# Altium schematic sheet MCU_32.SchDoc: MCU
size A4; DocumentNumber: MB1180; Revision: C.1; SheetNumber: 2; SheetTotal: 3; Project: NUCLEO32
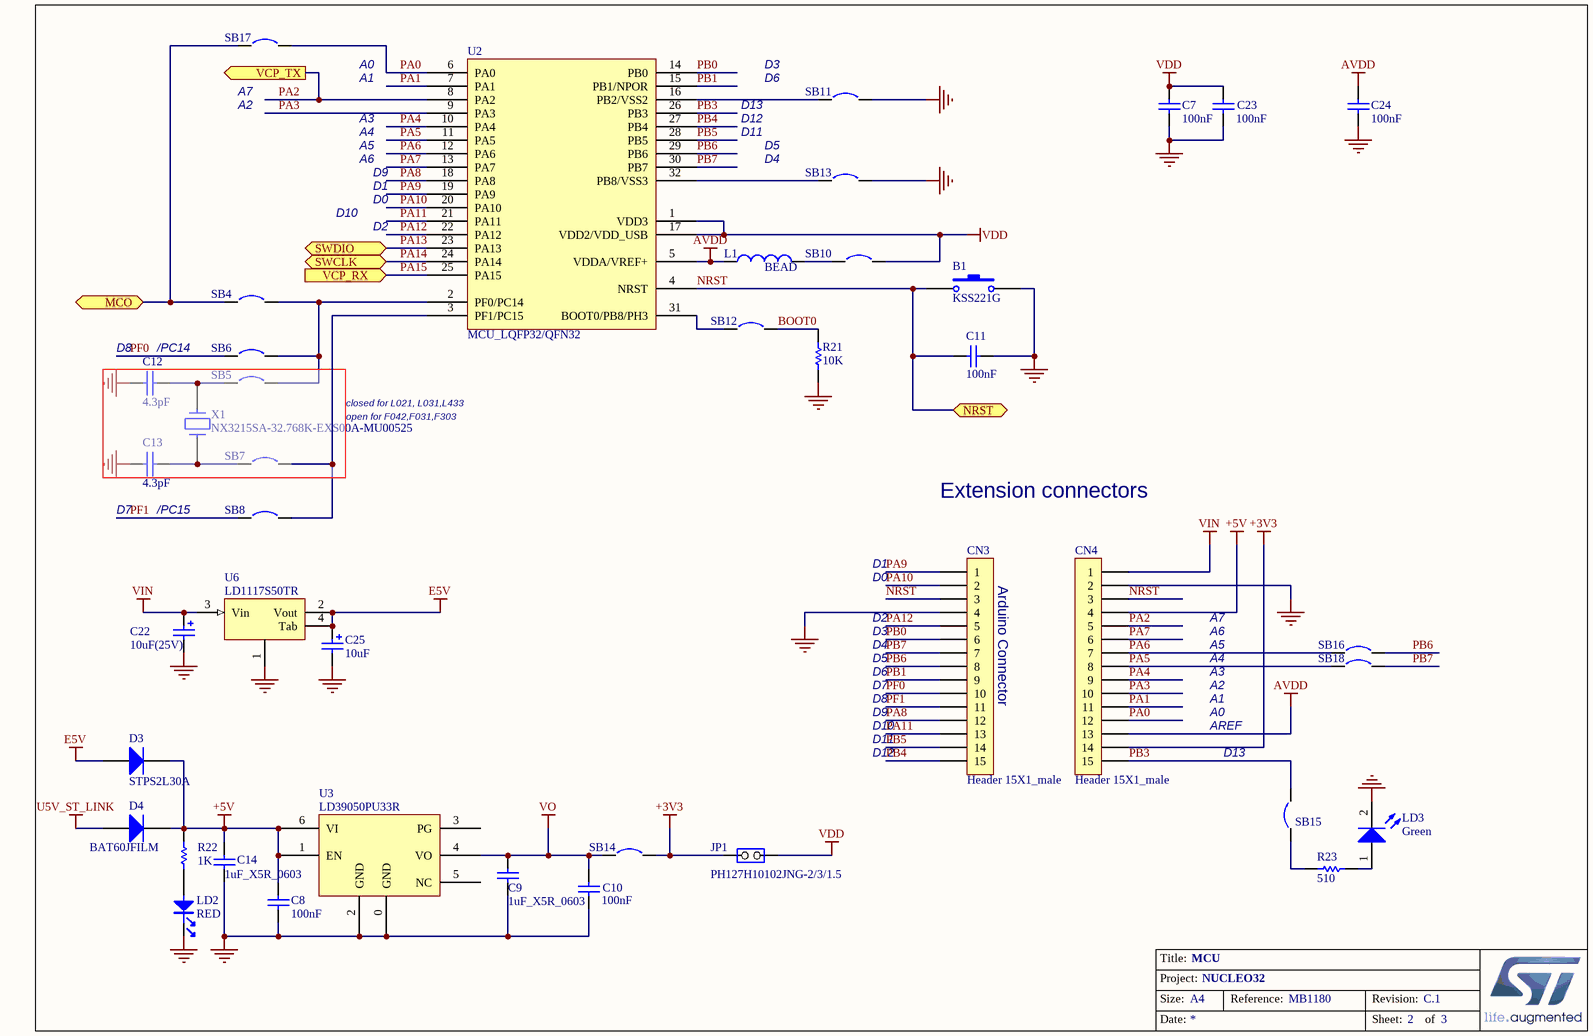
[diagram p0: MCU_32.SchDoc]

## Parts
B1  KSS221G  [SW2_5R6_5R5x3R1]
C7  100nF  [0603C]
C8  100nF  [0603C]
C9  1uF_X5R_0603  [0603C]
C10  100nF  [0603C]
C11  100nF  [0603C]
C12  4.3pF  [0603C]
C13  4.3pF  [0603C]
C14  1uF_X5R_0603  [0603C]
C22  10uF(25V)  [TAN_B]
C23  100nF  [0603C]
C24  100nF  [0603C]
C25  10uF  [TAN_A]
CN3  Header 15X1_male  [HDR_1x15_2R54_V_F]
CN4  Header 15X1_male  [HDR_1x15_2R54_V_F]
D3  STPS2L30A  [SMA]
D4  BAT60JFILM  [SOD-323]
JP1  PH127H10102JNG-2/3/1.5  [HDR_1x2_1R27_R_M]
L1  BEAD  [0603L]
LD2  RED  [0603D_R]
LD3  Green  [0603D_G]
R21  10K  [0603R]
R22  1K  [0603R]
R23  510  [0603R]
SB4  Circuit Breaker (open)  [SB_0603]  (value not drawn)
SB5  Circuit Breaker  [SB_0603]  (value not drawn)
SB6  Circuit Breaker  [SB_0603]  (value not drawn)
SB7  Circuit Breaker  [SB_0603]  (value not drawn)
SB8  Circuit Breaker  [SB_0603]  (value not drawn)
SB10  Circuit Breaker (close)  [SB_0603]  (value not drawn)
SB11  Circuit Breaker (close)  [SB_0603]  (value not drawn)
SB12  Circuit Breaker (close)  [SB_0603]  (value not drawn)
SB13  Circuit Breaker (close)  [SB_0603]  (value not drawn)
SB14  Circuit Breaker (close)  [SB_0603]  (value not drawn)
SB15  Circuit Breaker (close)  [SB_0603]  (value not drawn)
SB16  Circuit Breaker (close)  [SB_0603]  (value not drawn)
SB17  Circuit Breaker (open)  [SB_0603]  (value not drawn)
SB18  Circuit Breaker (close)  [SB_0603]  (value not drawn)
U2  MCU_LQFP32/QFN32  [LQFP32_0R5_7x7]
U3  LD39050PU33R  [DFN6_0R95_3x3_TP]
U6  LD1117S50TR  [SOT-223]
X1  NX3215SA-32.768K-EXS00A-MU00525  [XTAL_2SM_3R2X1R5]

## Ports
MCO, NRST, SWCLK, SWDIO, VCP_RX (in), VCP_TX (out)

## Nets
+3V3: CN4.14 JP1.1(COMMON) SB14.2
+5V: C8.2 C14.1 CN4.4 D3.2(K) D4.2(K) R22.2 U3.1(EN) U3.6(VI)
AVDD: C24.1 CN4.13 L1.1 U2.5(VDDA/VREF+)
E5V: C25.1 D3.1(A) U6.2(Vout) U6.4(Tab)
GND: B1.2 C7.2 C8.1 C9.2 C10.1 C11.1 C12.2 C13.2 C14.2 C22.2 C23.2 C24.2 C25.2 CN3.4 CN4.2 LD2.2 LD3.2(K) R21.2 SB11.2 SB13.2 U3.0(GND) U3.2(GND) U6.1
U5V_ST_LINK: D4.1(A)
VDD: C7.1 C23.1 JP1.2(NO) SB10.2 U2.1(VDD3) U2.17(VDD2/VDD_USB)
VIN: C22.1 CN4.1 U6.3(Vin)
VO: C9.1 C10.2 SB14.1 U3.4(VO)
BOOT0: R21.1 SB12.2
MCO: SB4.1 SB17.1 ; port MCO
NRST: B1.1 C11.2 CN3.3 CN4.3 U2.4(NRST) ; port NRST
PA0: CN4.12 SB17.2 U2.6(PA0)
PA1: CN4.11 U2.7(PA1)
PA2: CN4.5 U2.8(PA2) ; port VCP_TX
PA3: CN4.10 U2.9(PA3)
PA4: CN4.9 U2.10(PA4)
PA5: CN4.8 SB18.1 U2.11(PA5)
PA6: CN4.7 SB16.1 U2.12(PA6)
PA7: CN4.6 U2.13(PA7)
PA8: CN3.12 U2.18(PA8)
PA9: CN3.1 U2.19(PA9)
PA10: CN3.2 U2.20(PA10)
PA11: CN3.13 U2.21(PA11)
PA12: CN3.5 U2.22(PA12)
PA13: U2.23(PA13) ; port SWDIO
PA14: U2.24(PA14) ; port SWCLK
PA15: U2.25(PA15) ; port VCP_RX
PB0: CN3.6 U2.14(PB0)
PB1: CN3.9 U2.15(PB1/NPOR)
PB3: CN4.15 SB15.2 U2.26(PB3)
PB4: CN3.15 U2.27(PB4)
PB5: CN3.14 U2.28(PB5)
PB6: CN3.8 SB16.2 U2.29(PB6)
PB7: CN3.7 SB18.2 U2.30(PB7)
PF0: CN3.10 SB6.1
PF1: CN3.11 SB8.1
NetC12_1: C12.1 SB5.1 X1.1
NetC13_1: C13.1 SB7.1 X1.2
NetL1_2: L1.2 SB10.1
NetLD2_1: LD2.1 R22.1
NetLD3_1: LD3.1(A) R23.1
NetR23_2: R23.2 SB15.1
NetSB4_2: SB4.2 SB5.2 SB6.2 U2.2(PF0/PC14)
NetSB7_2: SB7.2 SB8.2 U2.3(PF1/PC15)
NetSB11_1: SB11.1 U2.16(PB2/VSS2)
NetSB12_1: SB12.1 U2.31(BOOT0/PB8/PH3)
NetSB13_1: SB13.1 U2.32(PB8/VSS3)

Not connected (* = marked no-connect by the designer): U3 3(PG) 5(NC)

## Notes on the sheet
- A2
- (near SB17) A7
- A0
- A1
- D3
- (near SB11) D13
- D6
- A3
- A5
- A6
- A4
- D9
- D4
- D11
- D12
- D5
- D10
- D0
- D1
- D2
- (near C12) D8
- (near C12) /PC14
- closed for L021, L031,L433
- open for F042,F031,F303
- (near C13) D7
- /PC15
- Extension connectors
- (near CN3) Arduino Connector
- A7
- D7
- D8
- AREF
- D13

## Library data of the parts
B1 = SW-PB: Switch
C7 C23 C24 = Cap: Capacitor; Value: 10nF
C8 C10 = Capacitor_ST: Capacitor 0402 / 0603 / 0805
C9 C14 = CAP SMD 0603  X5R 1µF 25V 10%: 0603  X5R 1µF; Rated voltage: 25V; Tolerance: 10%
C11 = CAP: Capacitor; Value: 100pF
C12 C13 = CAP: Capacitor
C22 C25 = Cap Pol1: Polarized Capacitor (Radial)
CN3 CN4 = Header 15X1_Female_1: Header, 10-Pin, Single row,female
D3 = STPS2L30A: Manuf_1: STM; Provided: ST; Order: BAT60JFILM; ECCN_US/EU: EAR99/NEC
D4 = BAT60JFILM: Manuf_1: STM; Provided: ST; ECCN_US/EU: EAR99/NEC
JP1 = JP2
L1 = Inductor: Value: 100uH
LD2 = PHOTO
LD3 = LED2: Typical RED, GREEN, YELLOW, AMBER GaAs LED
R21 = res1: Resistor; Value: 1K
R22 = Resistor_ST: Resistor 0402 / 0603 / 0805; Description: Resistor 0402 or 0603 or 0805; Value: 10K
R23 = Res1: Resistor; Value: 1K
SB4-SB8 SB10-SB18 = Circuit Breaker: Solder: NO
U2 = MCU_LQFP32
U3 = LD39050P
U6 = LD1117
X1 = CRYSTAL_32K: Crystal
